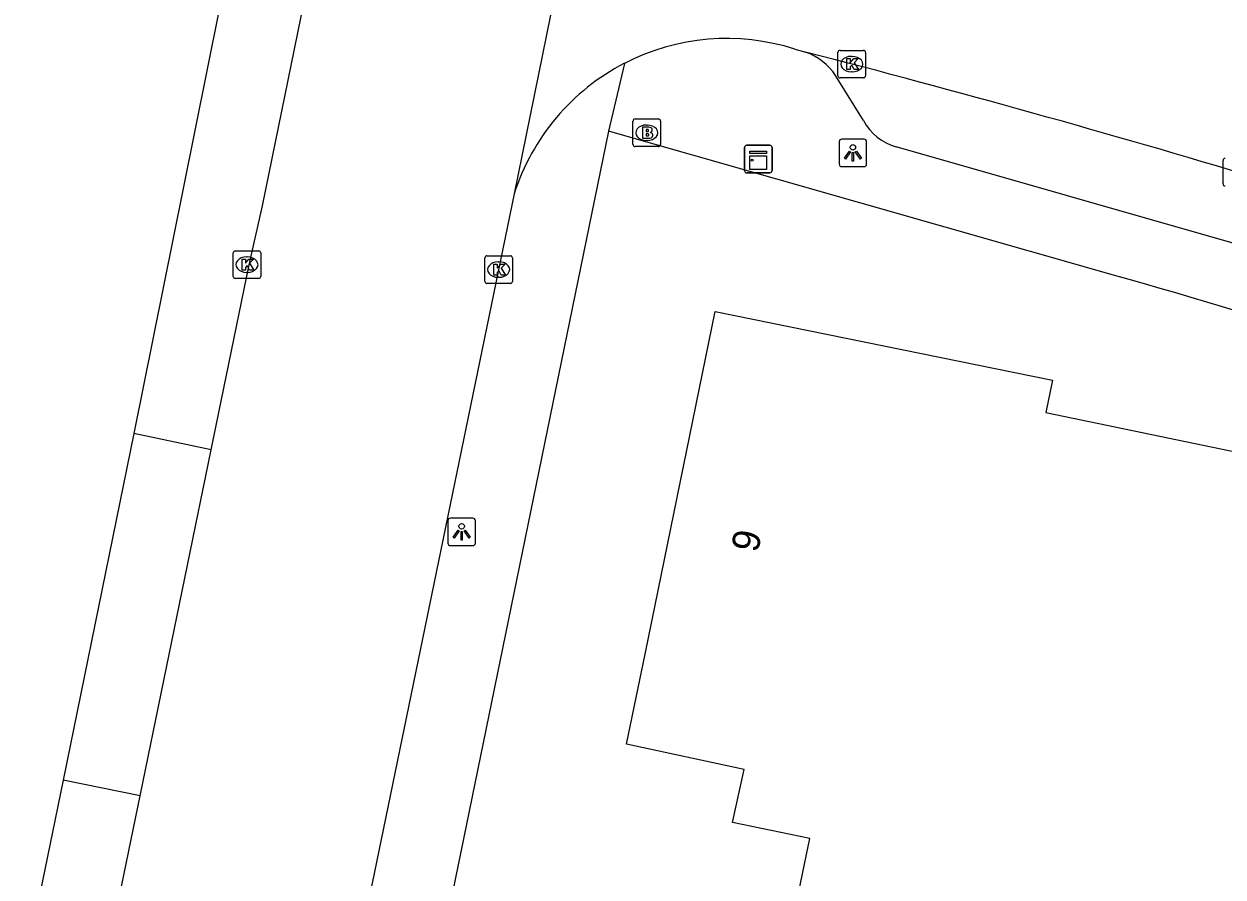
# Model space of a CAD drawing. Extents: x 157692 to 159670, y 381454 to 383289.
# Drawn here: x 158075.63 to 158119.18, y 381831.37 to 381862.34 of the extents above; entities that cross this region are included whole.
import ezdxf

# ---------------------------------------------------------------- set-up
doc = ezdxf.new("R2010")
doc.units = 0
for name, color, linetype in [('IMGEO_Brandkraan', 7, 'Continuous'), ('IMGEO_Kast', 7, 'Continuous'), ('IMGEO_Kolk', 7, 'Continuous'), ('IMGEO_Lichtpunt', 7, 'Continuous'), ('IMGEO_Pand', 7, 'Continuous'), ('IMGEO_Pand_nummerreeks', 7, 'Continuous'), ('IMGEO_Rijbaan_lokaal_gesloten', 7, 'Continuous'), ('IMGEO_Voetpad_open', 7, 'Continuous')]:
    doc.layers.add(name, color=color, linetype=linetype)

msp = doc.modelspace()

# ---------------------------------------------------------------- linework, layer by layer
at = {"layer": 'IMGEO_Brandkraan'}
for p, q in [((158097.822, 381858.889), (158098.674, 381858.889)), ((158097.747, 381857.963), (158097.747, 381858.815)), ((158098.235, 381858.669), (158098.26, 381858.669)), ((158098.748, 381858.815), (158098.748, 381857.963)), ((158098.258, 381858.109), (158098.233, 381858.109)), ((158098.674, 381857.889), (158097.822, 381857.889))]:
    msp.add_line(p, q, dxfattribs=at)
for points in [[(158097.822, 381858.889), (158098.674, 381858.889)], [(158097.747, 381857.963), (158097.747, 381858.815)], [(158098.095, 381858.589), (158098.095, 381858.189), (158098.308, 381858.189)], [(158098.326, 381858.589), (158098.095, 381858.589)], [(158098.274, 381858.508), (158098.22, 381858.508), (158098.22, 381858.432)], [(158098.22, 381858.432), (158098.273, 381858.432)], [(158098.748, 381858.815), (158098.748, 381857.963)], [(158098.282, 381858.356), (158098.22, 381858.356), (158098.22, 381858.275)], [(158098.22, 381858.275), (158098.282, 381858.275)], [(158098.674, 381857.889), (158097.822, 381857.889)]]:
    msp.add_lwpolyline(points, dxfattribs=at)
for centre, radius, start, end in [((158097.824, 381858.813), 0.0765, 91.552, 178.448), ((158097.824, 381858.813), 0.0765, 91.552, 178.448), ((158098.672, 381858.813), 0.0765, 1.552, 88.448), ((158098.672, 381858.813), 0.0765, 1.552, 88.448), ((158098.275, 381858.47), 0.0379, 267.8285, 90.9355), ((158098.33, 381858.444), 0.145, 59.4692, 91.5367), ((158098.355, 381858.491), 0.0922, 285.5137, 58.1501), ((158098.283, 381858.315), 0.0404, 269.8759, 90.5077), ((158098.314, 381858.44), 0.251, 268.6676, 293.5347), ((158098.36, 381858.299), 0.105, 301.3115, 78.989), ((158097.824, 381857.965), 0.0765, 181.552, 268.448), ((158097.824, 381857.965), 0.0765, 181.552, 268.448), ((158098.672, 381857.965), 0.0765, 271.552, 358.448), ((158098.672, 381857.965), 0.0765, 271.552, 358.448)]:
    msp.add_arc(centre, radius, start, end, dxfattribs=at)
for centre, major_axis, ratio, start_param, end_param in [((158098.234, 381858.389), (-0.387, 0.002), 0.722429, 4.712389, 7.853982), ((158098.259, 381858.389), (-0.39, 0.002), 0.717154, 1.570796, 4.712389)]:
    msp.add_ellipse(centre, major_axis=major_axis, ratio=ratio, start_param=start_param, end_param=end_param, dxfattribs=at)
at = {"layer": 'IMGEO_Kast'}
for p, q in [((158101.797, 381857.008), (158101.797, 381857.849)), ((158101.797, 381857.849), (158101.797, 381857.008)), ((158101.872, 381857.933), (158102.713, 381857.933)), ((158102.713, 381857.933), (158101.872, 381857.933)), ((158102.797, 381857.858), (158102.797, 381857.017)), ((158102.797, 381857.017), (158102.797, 381857.858)), ((158102.722, 381856.933), (158101.881, 381856.933)), ((158101.881, 381856.933), (158102.722, 381856.933))]:
    msp.add_line(p, q, dxfattribs=at)
for points in [[(158101.992, 381857.723), (158102.592, 381857.723), (158102.592, 381857.638), (158101.992, 381857.638), (158101.992, 381857.723)], [(158101.992, 381857.548), (158102.592, 381857.548), (158102.592, 381857.059), (158101.992, 381857.059), (158101.992, 381857.548)]]:
    msp.add_lwpolyline(points, dxfattribs=at)
msp.add_circle((158102.076, 381857.397), 0.0377, dxfattribs=at)
for centre, start, end in [((158101.875, 381857.855), 92.4484, 184.2845), ((158101.875, 381857.855), 92.4484, 184.2845), ((158102.719, 381857.855), 2.4484, 94.2845), ((158102.719, 381857.855), 2.4484, 94.2845), ((158101.875, 381857.011), 182.4484, 274.2845), ((158101.875, 381857.011), 182.4484, 274.2845), ((158102.719, 381857.011), 272.4484, 4.2845), ((158102.719, 381857.011), 272.4484, 4.2845)]:
    msp.add_arc(centre, 0.0779, start, end, dxfattribs=at)
at = {"layer": 'IMGEO_Kolk'}
for p, q in [((158105.192, 381860.455), (158105.192, 381861.307)), ((158105.267, 381861.381), (158106.119, 381861.381)), ((158105.68, 381861.161), (158105.705, 381861.161)), ((158106.193, 381861.307), (158106.193, 381860.455)), ((158105.703, 381860.601), (158105.678, 381860.601)), ((158106.119, 381860.381), (158105.267, 381860.381)), ((158119.176, 381856.532), (158119.176, 381857.384)), ((158083.301, 381854.101), (158084.153, 381854.101)), ((158083.226, 381853.175), (158083.226, 381854.027)), ((158083.714, 381853.881), (158083.739, 381853.881)), ((158084.227, 381854.027), (158084.227, 381853.175)), ((158092.367, 381852.995), (158092.367, 381853.847)), ((158092.442, 381853.921), (158093.294, 381853.921)), ((158092.855, 381853.701), (158092.88, 381853.701)), ((158093.368, 381853.847), (158093.368, 381852.995)), ((158083.737, 381853.321), (158083.712, 381853.321)), ((158084.153, 381853.101), (158083.301, 381853.101)), ((158093.294, 381852.921), (158092.442, 381852.921)), ((158092.878, 381853.141), (158092.853, 381853.141))]:
    msp.add_line(p, q, dxfattribs=at)
for points in [[(158105.192, 381860.455), (158105.192, 381861.307)], [(158105.267, 381861.381), (158106.119, 381861.381)], [(158105.513, 381861.081), (158105.636, 381861.081), (158105.636, 381860.93), (158105.766, 381861.081), (158105.93, 381861.081), (158105.784, 381860.93), (158105.937, 381860.681), (158105.785, 381860.681), (158105.7, 381860.845), (158105.636, 381860.778), (158105.636, 381860.681), (158105.513, 381860.681), (158105.513, 381861.081)], [(158106.193, 381861.307), (158106.193, 381860.455)], [(158106.119, 381860.381), (158105.267, 381860.381)], [(158119.176, 381856.532), (158119.176, 381857.384)], [(158083.301, 381854.101), (158084.153, 381854.101)], [(158083.226, 381853.175), (158083.226, 381854.027)], [(158083.547, 381853.801), (158083.67, 381853.801), (158083.67, 381853.65), (158083.8, 381853.801), (158083.964, 381853.801), (158083.818, 381853.65), (158083.971, 381853.401), (158083.819, 381853.401), (158083.734, 381853.565), (158083.67, 381853.498), (158083.67, 381853.401), (158083.547, 381853.401), (158083.547, 381853.801)], [(158084.227, 381854.027), (158084.227, 381853.175)], [(158092.367, 381852.995), (158092.367, 381853.847)], [(158092.442, 381853.921), (158093.294, 381853.921)], [(158093.368, 381853.847), (158093.368, 381852.995)], [(158092.688, 381853.621), (158092.811, 381853.621), (158092.811, 381853.47), (158092.941, 381853.621), (158093.105, 381853.621), (158092.959, 381853.47), (158093.112, 381853.221), (158092.96, 381853.221), (158092.875, 381853.385), (158092.811, 381853.318), (158092.811, 381853.221), (158092.688, 381853.221), (158092.688, 381853.621)], [(158084.153, 381853.101), (158083.301, 381853.101)], [(158093.294, 381852.921), (158092.442, 381852.921)]]:
    msp.add_lwpolyline(points, dxfattribs=at)
for centre, start, end in [((158105.269, 381861.305), 91.552, 178.448), ((158105.269, 381861.305), 91.552, 178.448), ((158106.117, 381861.305), 1.552, 88.448), ((158106.117, 381861.305), 1.552, 88.448), ((158105.269, 381860.457), 181.552, 268.448), ((158105.269, 381860.457), 181.552, 268.448), ((158106.117, 381860.457), 271.552, 358.448), ((158106.117, 381860.457), 271.552, 358.448), ((158119.253, 381857.382), 91.552, 178.448), ((158119.253, 381857.382), 91.552, 178.448), ((158119.253, 381856.534), 181.552, 268.448), ((158119.253, 381856.534), 181.552, 268.448), ((158083.303, 381854.025), 91.552, 178.448), ((158083.303, 381854.025), 91.552, 178.448), ((158084.151, 381854.025), 1.552, 88.448), ((158084.151, 381854.025), 1.552, 88.448), ((158092.444, 381853.845), 91.552, 178.448), ((158092.444, 381853.845), 91.552, 178.448), ((158093.292, 381853.845), 1.552, 88.448), ((158093.292, 381853.845), 1.552, 88.448), ((158083.303, 381853.177), 181.552, 268.448), ((158083.303, 381853.177), 181.552, 268.448), ((158084.151, 381853.177), 271.552, 358.448), ((158084.151, 381853.177), 271.552, 358.448), ((158092.444, 381852.997), 181.552, 268.448), ((158092.444, 381852.997), 181.552, 268.448), ((158093.292, 381852.997), 271.552, 358.448), ((158093.292, 381852.997), 271.552, 358.448)]:
    msp.add_arc(centre, 0.0765, start, end, dxfattribs=at)
for centre, major_axis, ratio, start_param, end_param in [((158105.679, 381860.881), (-0.387, 0.002), 0.722429, 4.712389, 7.853982), ((158105.704, 381860.881), (-0.39, 0.002), 0.717154, 1.570796, 4.712389), ((158083.713, 381853.601), (-0.387, 0.002), 0.722429, 4.712389, 7.853982), ((158083.738, 381853.601), (-0.39, 0.002), 0.717154, 1.570796, 4.712389), ((158092.854, 381853.421), (-0.387, 0.002), 0.722429, 4.712389, 7.853982), ((158092.879, 381853.421), (-0.39, 0.002), 0.717154, 1.570796, 4.712389)]:
    msp.add_ellipse(centre, major_axis=major_axis, ratio=ratio, start_param=start_param, end_param=end_param, dxfattribs=at)
at = {"layer": 'IMGEO_Lichtpunt'}
for p, q in [((158105.236, 381858.062), (158105.236, 381857.255)), ((158105.236, 381858.062), (158105.236, 381857.255)), ((158106.138, 381858.157), (158105.33, 381858.157)), ((158106.138, 381858.157), (158105.33, 381858.157)), ((158106.232, 381857.255), (158106.232, 381858.062)), ((158106.232, 381857.255), (158106.232, 381858.062)), ((158105.33, 381857.161), (158106.138, 381857.161)), ((158105.33, 381857.161), (158106.138, 381857.161)), ((158091.025, 381844.301), (158091.025, 381843.494)), ((158091.025, 381844.301), (158091.025, 381843.494)), ((158091.927, 381844.396), (158091.119, 381844.396)), ((158091.927, 381844.396), (158091.119, 381844.396)), ((158092.021, 381843.494), (158092.021, 381844.301)), ((158092.021, 381843.494), (158092.021, 381844.301)), ((158091.119, 381843.4), (158091.927, 381843.4)), ((158091.119, 381843.4), (158091.927, 381843.4))]:
    msp.add_line(p, q, dxfattribs=at)
for points in [[(158105.61, 381857.726), (158105.649, 381857.698), (158105.461, 381857.436), (158105.423, 381857.463), (158105.61, 381857.726)], [(158105.712, 381857.678), (158105.759, 381857.678), (158105.759, 381857.356), (158105.712, 381857.356), (158105.712, 381857.678)], [(158105.822, 381857.698), (158105.86, 381857.725), (158106.047, 381857.463), (158106.008, 381857.435), (158105.822, 381857.698)], [(158091.399, 381843.965), (158091.438, 381843.937), (158091.25, 381843.675), (158091.212, 381843.702), (158091.399, 381843.965)], [(158091.501, 381843.917), (158091.548, 381843.917), (158091.548, 381843.595), (158091.501, 381843.595), (158091.501, 381843.917)], [(158091.611, 381843.937), (158091.649, 381843.964), (158091.836, 381843.702), (158091.797, 381843.674), (158091.611, 381843.937)]]:
    msp.add_lwpolyline(points, dxfattribs=at)
for centre in [(158105.735, 381857.86), (158091.524, 381844.099)]:
    msp.add_circle(centre, 0.0994, dxfattribs=at)
for centre, start, end in [((158105.33, 381858.062), 90, 180), ((158105.33, 381858.062), 90, 180), ((158106.138, 381858.062), 0, 90), ((158106.138, 381858.062), 0, 90), ((158105.33, 381857.255), 180, 270), ((158105.33, 381857.255), 180, 270), ((158106.138, 381857.255), 270, 0), ((158106.138, 381857.255), 270, 360), ((158091.119, 381844.301), 90, 180), ((158091.119, 381844.301), 90, 180), ((158091.927, 381844.301), 0, 90), ((158091.927, 381844.301), 0, 90), ((158091.119, 381843.494), 180, 270), ((158091.119, 381843.494), 180, 270), ((158091.927, 381843.494), 270, 0), ((158091.927, 381843.494), 270, 360)]:
    msp.add_arc(centre, 0.0946, start, end, dxfattribs=at)
at = {"layer": 'IMGEO_Pand'}
msp.add_lwpolyline([(158102.734, 381825.813), (158104.044, 381832.191), (158104.164, 381832.773), (158101.359, 381833.35), (158101.783, 381835.271), (158097.517, 381836.193), (158098.197, 381839.516), (158100.733, 381851.905), (158112.978, 381849.405), (158112.74, 381848.239), (158123.532, 381845.992), (158122.559, 381841.327), (158130.579, 381839.658), (158131.276, 381843.007), (158136.07, 381841.995), (158140.855, 381840.985), (158140.175, 381837.654), (158151.738, 381835.295), (158150.734, 381830.397)], dxfattribs=at)
at = {"layer": 'IMGEO_Rijbaan_lokaal_gesloten'}
for points in [[(158082.429, 381846.881), (158083.809, 381853.599), (158084.29, 381855.738), (158089.883, 381883.116), (158090.046, 381883.911), (158093.994, 381903.198), (158098.681, 381926.231), (158099.043, 381927.911)], [(158098.248, 381879.541), (158098.112, 381879.211), (158093.435, 381856.17)], [(158103.62, 381861.429), (158103.888, 381861.351), (158104.017, 381861.318)], [(158093.435, 381856.17), (158087.271, 381826.269)], [(158079.85, 381834.323), (158082.429, 381846.881)], [(158078.425, 381827.386), (158079.85, 381834.323)]]:
    msp.add_lwpolyline(points, dxfattribs=at)
for centre, radius, start, end in [((158101.156, 381853.709), 8.103, 72.3016, 117.3147), ((157995.02, 381438.686), 436.461, 73.29584, 75.53852), ((158101.153, 381853.711), 8.101, 117.299, 162.3259)]:
    msp.add_arc(centre, radius, start, end, dxfattribs=at)
at = {"layer": 'IMGEO_Voetpad_open'}
for points in [[(158089.467, 381896.422), (158087.078, 381884.542), (158081.414, 381856.37), (158079.616, 381847.467)], [(158097.438, 381860.909), (158096.863, 381858.446)], [(158106.117, 381858.832), (158105.104, 381860.473)], [(158096.863, 381858.446), (158090.285, 381826.377)], [(158115.195, 381853.221), (158096.863, 381858.446)], [(158119.745, 381854.323), (158107.306, 381857.884)], [(158079.616, 381847.467), (158077.048, 381834.888)], [(158082.429, 381846.881), (158079.616, 381847.467)], [(158077.048, 381834.888), (158075.628, 381827.934)], [(158079.85, 381834.323), (158077.048, 381834.888)]]:
    msp.add_lwpolyline(points, dxfattribs=at)
for centre, radius, start, end in [((158103.269, 381859.234), 2.214, 34.028, 70.2513), ((158107.79, 381859.71), 1.889, 207.7009, 255.1678), ((158054.025, 381634.974), 226.658, 69.58203, 74.34294)]:
    msp.add_arc(centre, radius, start, end, dxfattribs=at)

# ---------------------------------------------------------------- texts
at = {"layer": 'IMGEO_Pand_nummerreeks'}
msp.add_text('9', height=1, rotation=78.4322, dxfattribs=at).set_placement((158102.283, 381843.121))

doc.saveas('drawing.dxf')
